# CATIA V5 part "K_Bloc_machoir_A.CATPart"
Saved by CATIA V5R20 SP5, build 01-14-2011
Part number: bloc_machoir_1
Bounding box of the stored display mesh (mm): x -32.071 to 17.929, y -56.771 to 28.229, z 0 to 25
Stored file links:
  G:\Khaled_CFAO_2011\SIL\SIL_GR1\mroland\Khaled\CAD_CATIA_Modifie\K_Bloc_machoir_A.CATPart
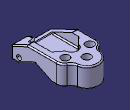
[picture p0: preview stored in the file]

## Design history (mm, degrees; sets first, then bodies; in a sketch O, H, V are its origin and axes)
Set1
  Sketch1 on xy-plane, origin (0, 0, 0), H (1, 0, 0), V (0, 1, 0)
    point P1 (-32.0711, 0)
    line L1 (-32.0711, 0) -> (-32.0711, -56.7712)
    line L2 (-32.0711, -56.7712) -> (17.9289, -56.7712)
    line L3 (17.9289, -56.7712) -> (17.9289, 0)
    point P4 (17.9289, 0)
    arc A1 centre (7.9289, 0) radius 10 from (17.9289, 0) to (13.0826, 8.5697) ccw
    point P5 (7.9289, 0)
    point P6 (17.9289, 0)
    arc A2 centre (-7.0711, 13.2288) radius 15 from (7.6161, 16.276) to (-21.9589, 15.0594) ccw
    point P7 (-7.0711, 13.2288)
    point P8 (0, 26.4575)
    arc A3 centre (-22.0711, 0) radius 10 from (-26.3136, 9.0554) to (-32.0711, 0) ccw
    point P9 (-22.0711, 0)
    point P10 (-32.0711, 0)
    arc A4 centre (-29.5647, 15.9947) radius 7.6631 from (-21.9589, 15.0594) to (-26.3136, 9.0554) cw
    arc A5 centre (19.1569, 18.6704) radius 11.7865 from (7.6161, 16.276) to (13.0826, 8.5697) ccw
    distance P9 A3 = 10
    distance P5 A1 = 10
    distance P7 A2 = 15
    distance P7 P9 = 20
    distance P7 P5 = 20
    distance P5 P9 = 30
    distance L2 A2 = 85
    radius A4 = 7.6631
    radius A5 = 11.7865
    coincidence: P1 H, P4 H, A1 P6, P6 L3, A2 P8, P8 V, A2 O, A3 P10, P10 L1
    vertical: L1 V, L3 V
    horizontal: L2 H
    tangency: A3 L1, L3 A1, A4 A2, A4 A3, A5 A2, A5 A1
Body1 (main body)
  Pad1: profile Sketch1, direction (0, 0, 1), length 25
  Sketch2 on end face of Pad1, origin (-8.9228, 9.7204, 25), H (1, 0, 0), V (0, 1, 0)
    point P1 (1.8517, 3.5083)
    reference projected arc E1 centre (1.8517, 3.5083) radius 15 from (16.5389, 6.5556) to (-13.0362, 5.339) ccw from edge [face of Pad1 from Sketch1.A2 | end face of Pad1]
    concentricity: E1 P1
  Hole1: placed by Sketch2, at (-7.0711, 13.2288, 25) direction (0, 0, -1), diameter 10 {= 10mm}, through (limit type 3)
  Sketch3 on end face of Pad1, origin (-21.1049, 2.0333, 25), H (1, 0, 0), V (0, 1, 0)
    point P1 (28.4106, -1.4836)
    reference projected point E1 (14.0338, 11.1955) from axis of face of Hole1
    distance P1 E1 = 19.169
  Hole2: placed by Sketch3, at (7.3057, 0.5497, 25) direction (0, 0, -1), diameter 10, through (limit type 3)
  Sketch4 on end face of Pad1, origin (-9.8751, -18.0882, 25), H (1, 0, 0), V (0, 1, 0)
    point P1 (-12.8071, 19.4905)
    reference projected point E1 (2.804, 31.317) from axis of face of Hole1
    reference projected point E2 (17.1807, 18.6379) from axis of face of Hole2
    distance P1 E1 = 19.585
    distance P1 E2 = 30
  Hole3: placed by Sketch4, at (-22.6822, 1.4023, 25) direction (0, 0, -1), diameter 10, through (limit type 3)
  Sketch5 on face of Pad1 from Sketch1.L1, origin (-32.0711, 0, 0), H (0, -1, 0), V (0, 0, 1)
    point P1 (6.3466, 0)
    line L1 (6.3466, 0) -> (27.0589, 10)
    point P2 (27.0589, 10)
    line L2 (27.0589, 10) -> (47.7712, 0)
    point P3 (47.7712, 0)
    line L3 (47.7712, 0) -> (6.3466, 0)
    reference projected line E1 (56.7712, 0) -> (56.7712, 25) from edge [face of Pad1 from Sketch1.L2 | face of Pad1 from Sketch1.L1]
    distance P3 E1 = 9
    length L2 = 23
    length L1 = 23
    distance P2 L3 = 10
    coincidence: P1 H, P3 H
    horizontal: L3 H
  Pocket1: profile Sketch5, direction (1, 0, 0), through (limit type 3)
  Sketch6 on face of Pad1 from Sketch1.L1, origin (-32.0711, 0, 0), H (0, -1, 0), V (0, 0, 1)
    line L1 (22.4405, 25) -> (56.7712, 8.4249)
    line L2 (56.7712, 8.4249) -> (56.7712, 25)
    line L3 (56.7712, 25) -> (22.4405, 25)
    reference projected line E1 (56.7712, 0) -> (56.7712, 25) from edge [face of Pad1 from Sketch1.L2 | face of Pad1 from Sketch1.L1]
    reference projected line E2 (0, 25) -> (56.7712, 25) from edge [face of Pad1 from Sketch1.L1 | end face of Pad1]
    reference projected line E3 (47.7712, 0) -> (27.0589, 10) from edge [face of Pad1 from Sketch1.L1 | face of Pocket1 from Sketch5.L2]
    distance L1 E3 = 11.5
    vertical: L2 V
    horizontal: L3 H
    coincidence: E1 L2, L3 E2
  Pocket2: profile Sketch6, direction (1, 0, 0), length 30
  Sketch7 on end face of Pad1, origin (0, 0, 25), H (1, 0, 0), V (0, 1, 0)
    point P1 (9.9289, -13.7712)
    line L1 (9.9289, -13.7712) -> (9.9289, -42.0377)
    arc A1 centre (6.9896, -48.3907) radius 7 from (9.9289, -42.0377) to (0, -48.7712) ccw
    point P4 (0, -48.7712)
    line L2 (0, -48.7712) -> (-28, -48.7712)
    arc A2 centre (-28, -44.8423) radius 3.9289 from (-28, -48.7712) to (-24.0711, -44.8423) ccw
    line L3 (-24.0711, -44.8423) -> (-24.0711, -13.7712)
    point P8 (-24.0711, -13.7712)
    point P9 (-19.8667, -8.7132)
    arc A3 centre (-7.9156, -7.0208) radius 8 from (-15.894, -6.4329) to (0.0827, -6.8594) cw
    point P11 (-7.9156, -7.0208)
    point P13 (5.0761, -9.7109)
    reference projected line E1 (17.9289, -56.7712) -> (17.9289, 0) from edge [face of Pad1 from Sketch1.L3 | end face of Pad1]
    reference projected line E2 (-32.0711, 0) -> (-32.0711, -56.7712) from edge [face of Pad1 from Sketch1.L1 | end face of Pad1]
    reference projected line E3 (-32.0711, -56.7712) -> (-2.0711, -56.7712) from edge [face of Pad1 from Sketch1.L2 | face of Pocket2 from Sketch6.L1]
    reference projected circle E4 centre (7.3057, 0.5497) radius 5 from edge [end face of Pad1 | face of Hole2]
    reference projected circle E5 centre (-22.6822, 1.4023) radius 5 from edge [end face of Pad1 | face of Hole3]
    reference projected circle E6 centre (7.3057, 0.5497) radius 5 from edge [end face of Pad1 | face of Hole2]
    reference projected circle E7 centre (-22.6822, 1.4023) radius 5 from edge [end face of Pad1 | face of Hole3]
    line L4 (-15.894, -6.4329) -> (-24.0711, -13.7712)
    point P14 (-24.0711, -13.7712)
    line L5 (0.0827, -6.8594) -> (9.9289, -13.7712)
    distance E1 L1 = 8
    distance E2 L3 = 8
    distance L2 E3 = 8
    length L2 = 28
    distance P11 E4 = 12
    distance P11 E5 = 12
    radius A3 = 8
    distance P13 E6 = 5.5
    distance E7 P9 = 5.5
    distance P1 L2 = 35
    distance P8 L2 = 35
    radius A1 = 7
    vertical: L1 V, L3 V
    coincidence: P4 V, P14 L3, L4 P8, P8 P14
    horizontal: L2 H
    tangency: A2 L2, L3 A2
  Pocket3: profile Sketch7, direction (0, 0, -1), length 13
  Fillet1: radius 1.5, on edge [face of Pocket3 from Sketch7.L5 | end face of Pocket3]
  Fillet2: radius 1.5, on edge [face of Pocket3 from Sketch7.A3 | end face of Pocket3]
  Fillet3: radius 1.5, on edge [face of Pocket3 from Sketch7.L1 | end face of Pocket3]
  Fillet4: radius 1.5, on edge [face of Pocket3 from Sketch7.L4 | end face of Pocket3]
  Fillet5: radius 1.5, on edge [face of Pocket3 from Sketch7.L3 | end face of Pocket3]
  Fillet6: radius 1.5, on edge [face of Pocket3 from Sketch7.A1 | end face of Pocket3]
  Fillet7: radius 1.5, on edge [face of Pocket3 from Sketch7.L2 | end face of Pocket3]
  Fillet8: radius 3, on edge [face of Pocket3 from Sketch7.A3 | face of Pocket3 from Sketch7.L5]
  Fillet9: radius 3, on edge [face of Pocket3 from Sketch7.L4 | face of Pocket3 from Sketch7.A3]
  Sketch8 on face of Pad1 from Sketch1.L3, origin (17.9289, 0, 0), H (0, 1, 0), V (0, 0, 1)
    line L1 (-56.7712, 25) -> (-56.7712, 15.3439)
    line L2 (-56.7712, 15.3439) -> (-36.7712, 25)
    line L3 (-36.7712, 25) -> (-56.7712, 25)
    reference projected line E1 (-56.7712, 25) -> (0, 25) from edge [face of Pad1 from Sketch1.L3 | end face of Pad1]
    reference projected line E2 (-56.7712, 0) -> (-56.7712, 25) from edge [face of Pad1 from Sketch1.L3 | face of Pad1 from Sketch1.L2]
    reference projected line E3 (-47.7712, 0) -> (-27.0589, 10) from edge [face of Pocket1 from Sketch5.L2 | face of Pad1 from Sketch1.L3]
    length L3 = 20
    vertical: L1 V
    horizontal: L3 H
    coincidence: L3 E1, L1 E2
    parallelism: L2 E3
  Pocket4: profile Sketch8, direction (-1, 0, 0), length 22
  Fillet10: radius 2, on edge [face of Pad1 from Sketch1.L2 | face of Pocket2 from Sketch6.L1]
  Fillet11: radius 1.5, on edge [start face of Pad1 | face of Pad1 from Sketch1.L2]
  Fillet12: radius 1.5, on edge [face of Pad1 from Sketch1.L1 | face of Pocket2 from Sketch6.L1]
  Fillet13: radius 1.5, on face of Pocket4 from Sketch8.L2
  Fillet14: radius 1.5, on edge [face of Pad1 from Sketch1.L2 | end face of Pocket2]
  Fillet15: radius 1.5, on edge [face of Pocket3 from Sketch7.L2 | end face of Pocket2]
  Fillet16: radius 1.5, on edge [face of Pad1 from Sketch1.L3 | face of Pad1 from Sketch1.L2]
  Fillet17: radius 1.5, on edge [face of Pad1 from Sketch1.L1 | face of Pocket1 from Sketch5.L2]
  Fillet18: radius 1.5, on edge [face of Pad1 from Sketch1.L1 | face of Pocket1 from Sketch5.L1]
  Fillet19: radius 1.5, on edge [start face of Pad1 | face of Pad1 from Sketch1.L1]
  Fillet20: radius 1.5, on edge [face of Pad1 from Sketch1.L1 | end face of Pad1]; edge [face of Pad1 from Sketch1.A3 | end face of Pad1]; edge [face of Pad1 from Sketch1.A4 | end face of Pad1]; edge [face of Pad1 from Sketch1.A2 | end face of Pad1]; edge [face of Pad1 from Sketch1.A5 | end face of Pad1]; edge [face of Pad1 from Sketch1.A1 | end face of Pad1]; edge [face of Pad1 from Sketch1.L3 | end face of Pad1]
  Fillet21: radius 1.5, on edge [face of Pad1 from Sketch1.L3 | face of Pocket1 from Sketch5.L1]
  Sketch9 on face of Pad1 from Sketch1.L1, origin (-32.0711, -42.294, 7.6497), H (0, 1, 0), V (0, 0, -1)
    point P1 (-5.0218, 1.1003)
    reference projected line E1 (13.5101, -3.1831) -> (-5.8204, 6.1497) from edge [face of Fillet17 | face of Pad1 from Sketch1.L1]
    distance P1 E1 = 4.2
  Hole4: placed by Sketch9, at (-32.0711, -47.3158, 6.5494) direction (1, 0, 0), diameter 6, through (limit type 3)
  Sketch10 on end face of Pad1, origin (0, 0, 25), H (1, 0, 0), V (0, 1, 0)
    point P1 (-32.0711, 0)
    line L1 (-32.0711, 0) -> (-32.0711, -56.7712)
    line L2 (-32.0711, -56.7712) -> (17.9289, -56.7712)
    line L3 (17.9289, -56.7712) -> (17.9289, 0)
    point P4 (17.9289, 0)
    arc A1 centre (7.9289, 0) radius 10 from (17.9289, 0) to (13.0826, 8.5697) ccw
    point P5 (7.9289, 0)
    point P6 (17.9289, 0)
    arc A2 centre (-7.0711, 13.2288) radius 15 from (7.6161, 16.276) to (-21.9589, 15.0594) ccw
    point P7 (-7.0711, 13.2288)
    point P8 (0, 26.4575)
    arc A3 centre (-22.0711, 0) radius 10 from (-26.3136, 9.0554) to (-32.0711, 0) ccw
    point P9 (-22.0711, 0)
    point P10 (-32.0711, 0)
    arc A4 centre (-29.5647, 15.9947) radius 7.6631 from (-21.9589, 15.0594) to (-26.3136, 9.0554) cw
    arc A5 centre (19.1569, 18.6704) radius 11.7865 from (7.6161, 16.276) to (13.0826, 8.5697) ccw
    distance P9 A3 = 10
    distance P5 A1 = 10
    distance P7 A2 = 15
    distance P7 P9 = 20
    distance P7 P5 = 20
    distance P5 P9 = 30
    distance L2 A2 = 85
    radius A4 = 7.6631
    radius A5 = 11.7865
    coincidence: P1 H, P4 H, A1 P6, P6 L3, A2 P8, P8 V, A2 O, A3 P10, P10 L1
    vertical: L1 V, L3 V
    horizontal: L2 H
    tangency: A3 L1, L3 A1, A4 A2, A4 A3, A5 A2, A5 A1
  Pad2: profile Sketch10, direction (0, 0, 1), length 25
Current feature: Hole4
